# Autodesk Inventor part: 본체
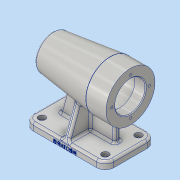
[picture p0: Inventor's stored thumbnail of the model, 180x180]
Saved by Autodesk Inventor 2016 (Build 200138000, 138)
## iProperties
Created: 2018-09
Part Number: 본체
Material: 알루미늄 6061
Document SubType Name: Modeling
Designer: 605-17
Density: 2.7 g/cm^3
Appearance: 알루미늄 - 평지
Mass: 731.223 g
Surface Area: 667.585 cm^2
Volume: 270.823 cm^3
Author: 605-17
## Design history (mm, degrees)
sketch "스케치2"
  geometry: L1 (-56, 35)-(56, 35); L2 (56, 35)-(56, -35); L3 (56, -35)-(-56, -35); L4 (-56, -35)-(-56, 35); 5 further points
  constraints: 8 end point, 4 horizontal alignment, 4 midpoint, 4 vertical alignment, 2 parallel, 1 horizontal, 1 perpendicular
  dimensions: "d0" = 112 distance of L1.start L1.end; "d1" = 70 distance of L3.end L1.start
extrude "돌출1" new body sketch "스케치2" distance "d2" = 10; taper "d3" = 0 deg
sketch "스케치3"
  geometry: L1 (56, 0)-(56, 10) reference; L2 (56, 74)-(-56, 74); L3 (-56, 74)-(-56, 108); L4 (-56, 108)-(-28, 108); L5 (-28, 108)-(52.27, 98.144); L6 (-56, 95)-(-41, 95); L7 (-41, 95)-(-41, 98); L8 (-41, 98)-(13, 98); L9 (13, 98)-(13, 95); L10 (13, 95)-(25, 95); L11 (25, 95)-(25, 91.5); L12 (25, 91.5)-(43, 91.5); L13 (43, 91.5)-(43, 90); L14 (43, 90)-(47, 90); L15 (47, 90)-(47, 84.5); L16 (47, 84.5)-(50, 84.5); L17 (50, 84.5)-(50, 74); A1 r 80 centre (-24, 74) between (52.27, 49.856) and (52.27, 98.144); 1 further point
  constraints: 32 end point, 11 perpendicular, 4 point on line, 3 point on circle, 2 vertical alignment, 1 centre point, 1 collinear, 1 horizontal, 1 horizontal alignment, 1 vertical
  dimensions: "d6" = 112 distance of L2.start L2.end; "d7" = 74 vertical distance of L2.start point (0, 0); "d9" = 7 deg angle of L5 L4; "d10" = 68 diameter of L4 L2; "d11" = 28 distance of L3.end L4.end; "d12" = 80 radius of A1; "d15" = 42 diameter of L6 L2; "d16" = 54 distance of L7.end L8.end; "d17" = 18 distance of L11.end L12.end; "d18" = 35 diameter of L12 L2; "d19" = 32 diameter of L14 L2; "d20" = 21 diameter of L16 L2; "d21" = 3 distance of L15.end L16.end; "d22" = 4 distance of L13.end L14.end; "d104" = 12 distance of L9.end L10.end; "d105" = 48 diameter of L8 L2; "d106" = 15 distance of L6.start L6.end
revolve "회전1" sketch "스케치3" stored, may be unused: angle "d23" = 90 deg
sketch "스케치4"
  geometry: C1 r 34 at (0, 0) reference; 2 further points
  constraints: 1 horizontal alignment
  dimensions: "d24" = 26 distance of C1.centre point (-26, 0)
hole "구멍1" sketch "스케치4" at (-26, 0) diameter "d25" = 3.242; stored, may be unused: countersink angle "d29" = 90 deg, drill point angle "d31" = 118 deg; dims "d26" = 8, "d27" = 4, "d28" = 2, "d30" = 11
fillet "모깎기1" dims "d35" = 12
fillet "모깎기2" dims "d36" = 3
sketch "스케치5"
  geometry: L1 (-35, 0)-(-35, 7) reference; L2 (35, 7)-(35, 0) reference; L3 (-34.819, 8.026)-(-18.467, 52.953); L4 (34.819, 8.026)-(18.467, 52.953); L5 (-23, 0)-(-35, 0) reference; L6 (-23, 0)-(23, 0) reference; L7 (35, 0)-(23, 0) reference; C1 r 24 at (0, 74) reference; A1 r 3 centre (-32, 7) between (-32, 10) and (-35, 7) reference; A2 r 3 centre (32, 7) between (35, 7) and (32, 10) reference; A3 r 28 centre (0, 74) between (-18.467, 52.953) and (18.467, 52.953); 1 further point
  constraints: 4 end point, 4 point on circle, 2 tangent, 1 centre point, 1 horizontal alignment
  dimensions: "d37" = 20 deg angle of L3 L1; "d38" = 28 radius of A3
extrude "돌출2" join sketch "스케치5" stored distance "d39" = 8; taper "d40" = 0 deg
sketch "스케치6"
  geometry: L1 (44, 10)-(4, 10) reference; L2 (44, 10)-(53, 10) reference; L3 (-4, 10)-(-44, 10) reference; L4 (-53, 10)-(-44, 10) reference; L5 (38, 10)-(27.282, 50); L6 (56, 0)-(56, 7) reference; L7 (-38, 10)-(-38, 43); L8 (-56, 7)-(-56, 0) reference; L9 (27.282, 50)-(-38, 43); L10 (38, 10)-(-38, 10); 1 further point
  constraints: 8 end point, 2 point on line, 1 horizontal, 1 vertical
  dimensions: "d41" = 105 deg angle of L5 L1; "d42" = 18 distance from line of L6 L5.start; "d43" = 18 distance between parallel lines of L8 L7; "d44" = 33 distance from line of L3 L7.end; "d45" = 40 distance from line of L1 L5.end
extrude "돌출3" join sketch "스케치6" stored distance "d46" = 8; taper "d47" = 0 deg
fillet "모깎기5" dims "d50" = 3
fillet "모깎기6" dims "d51" = 3
fillet "모깎기7" dims "d52" = 3
fillet "모깎기8" dims "d53" = 3
fillet "모깎기9" dims "d54" = 3
fillet "모깎기10" dims "d55" = 0.3
fillet "모깎기11" dims "d56" = 3
chamfer "모따기1" distance "d57" = 1; stored, may be unused: second distance "d58" = 2, angle "d59" = 45 deg
hole "구멍2" diameter "d62" = 5.5; stored, may be unused: countersink angle "d66" = 90 deg, drill point angle "d68" = 0 deg; dims "d60" = 10, "d61" = 10, "d63" = 8, "d64" = 9.5, "d65" = 5.4, "d67" = 11.8
hole "구멍3" diameter "d71" = 5.5; stored, may be unused: countersink angle "d75" = 90 deg, drill point angle "d77" = 0 deg; dims "d69" = 10, "d70" = 10, "d72" = 8, "d73" = 9.5, "d74" = 5.4, "d76" = 11.8
hole "구멍4" diameter "d80" = 5.5; stored, may be unused: countersink angle "d84" = 90 deg, drill point angle "d86" = 0 deg; dims "d78" = 10, "d79" = 10, "d81" = 8, "d82" = 9.5, "d83" = 5.4, "d85" = 11.8
hole "구멍5" diameter "d89" = 5.5; stored, may be unused: countersink angle "d93" = 90 deg, drill point angle "d95" = 0 deg; dims "d87" = 10, "d88" = 10, "d90" = 8, "d91" = 9.5, "d92" = 5.4, "d94" = 11.8
sketch "스케치7"
  geometry: L1 (-12, 7)-(-12, 0) reference; 2 further points
  constraints: 1 other
  dimensions: "d96" = 3 distance of point (44, 0) point (44, 3); "d97" = 56 distance from line of point (44, 3) L1
feature "엠보싱1" sketch "스케치7" dims "d0" = 112, "d1" = 70, "d98" = 0.5, "d99" = 0
fillet "모깎기12" dims "d100" = 3
node "솔리드1"
pattern_circular "원형 패턴1" dims angle "d33" = 360 deg
